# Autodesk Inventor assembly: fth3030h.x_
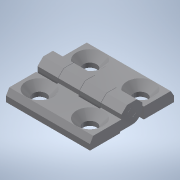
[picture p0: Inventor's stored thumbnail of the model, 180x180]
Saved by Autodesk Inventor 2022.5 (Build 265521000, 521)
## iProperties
Part Number: fth3030h.x_
Material: 一般
Document SubType Name: Assembly
Designer: ImaoCorp
Sending System: SOLIDWORKS 2017-2017317
MC: AMD64
MC_MODEL: Intel64 Family 6 Model 60 Stepping 3, GenuineIntel
OS: Windows_NT
FRU: Parasolid Version 29.0, build 201,  4-17-2017
FORMAT: text
GUISE: transmit
KEY: fth3030h
FILE: fth3030h.x_t
DATE: Mon May 13 14:29:06 2019
Author: ImaoCorp
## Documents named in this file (4)
- X:\14_SW2022-Inv2022\00_全2023-1023新製品(TCC)まで\f\fth3030h\FTH3030H.iam
- X:\14_SW2022-Inv2022\00_全2023-1023新製品(TCC)まで\f\fth3030h\fth3030h_01.ipt
- X:\14_SW2022-Inv2022\00_全2023-1023新製品(TCC)まで\f\fth3030h\fth3030h_02.ipt
- X:\14_SW2022-Inv2022\00_全2023-1023新製品(TCC)まで\f\fth3030h\fth3030h_03.ipt
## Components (3 placed, 3 different names)
1. fth3030h_01
2. fth3030h_02
3. fth3030h_03
